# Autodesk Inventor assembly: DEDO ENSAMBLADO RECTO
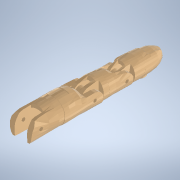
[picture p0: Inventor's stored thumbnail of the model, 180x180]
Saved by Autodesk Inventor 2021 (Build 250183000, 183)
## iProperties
Created: 2022-10
Part Number: DEDO ENSAMBLADO RECTO
Document SubType Name: Assembly
Designer: Yair Obed
Author: Yair Obed
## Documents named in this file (7)
- C:\Users\Yair Obed\Desktop\PROSTHESIS INDEX FINGER\DEDO ENSAMBLADO RECTO.iam
- C:\Users\Yair Obed\Desktop\PROSTHESIS INDEX FINGER\1 inventor.ipt
- C:\Users\Yair Obed\Desktop\PROSTHESIS INDEX FINGER\2 inventor.ipt
- C:\Users\Yair Obed\Desktop\PROSTHESIS INDEX FINGER\3 inventor.ipt
- C:\Users\Yair Obed\Desktop\PROSTHESIS INDEX FINGER\4 inventor.ipt
- C:\Users\Yair Obed\Desktop\PROSTHESIS INDEX FINGER\5 inventor.ipt
- C:\Users\Yair Obed\Desktop\PROSTHESIS INDEX FINGER\6 inventor.ipt
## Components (6 placed, 6 different names)
1. 1 inventor:1
2. 2 inventor:1
3. 3 inventor:1
4. 4 inventor:1
5. 5 inventor:1
6. 6 inventor:1
